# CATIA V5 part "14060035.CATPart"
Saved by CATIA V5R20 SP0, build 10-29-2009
Part number: 14060035
Definition: NONE
Nomenclature: 14060035
Source: Unknown
Description: 14060035
Bounding box of the stored display mesh (mm): x -17.5 to 70, y -44 to 33.913, z -34.1 to 34.1
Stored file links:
  C:\Users\Utente\Desktop\IO LAVORO\3D X SITO CF\X SITO\PLASTICA\RF2\14060035.CATPart
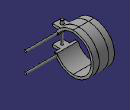
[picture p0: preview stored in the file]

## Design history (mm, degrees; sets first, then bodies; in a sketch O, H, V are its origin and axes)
Body1 "14060035" (main body)
  Solid1: solid without history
